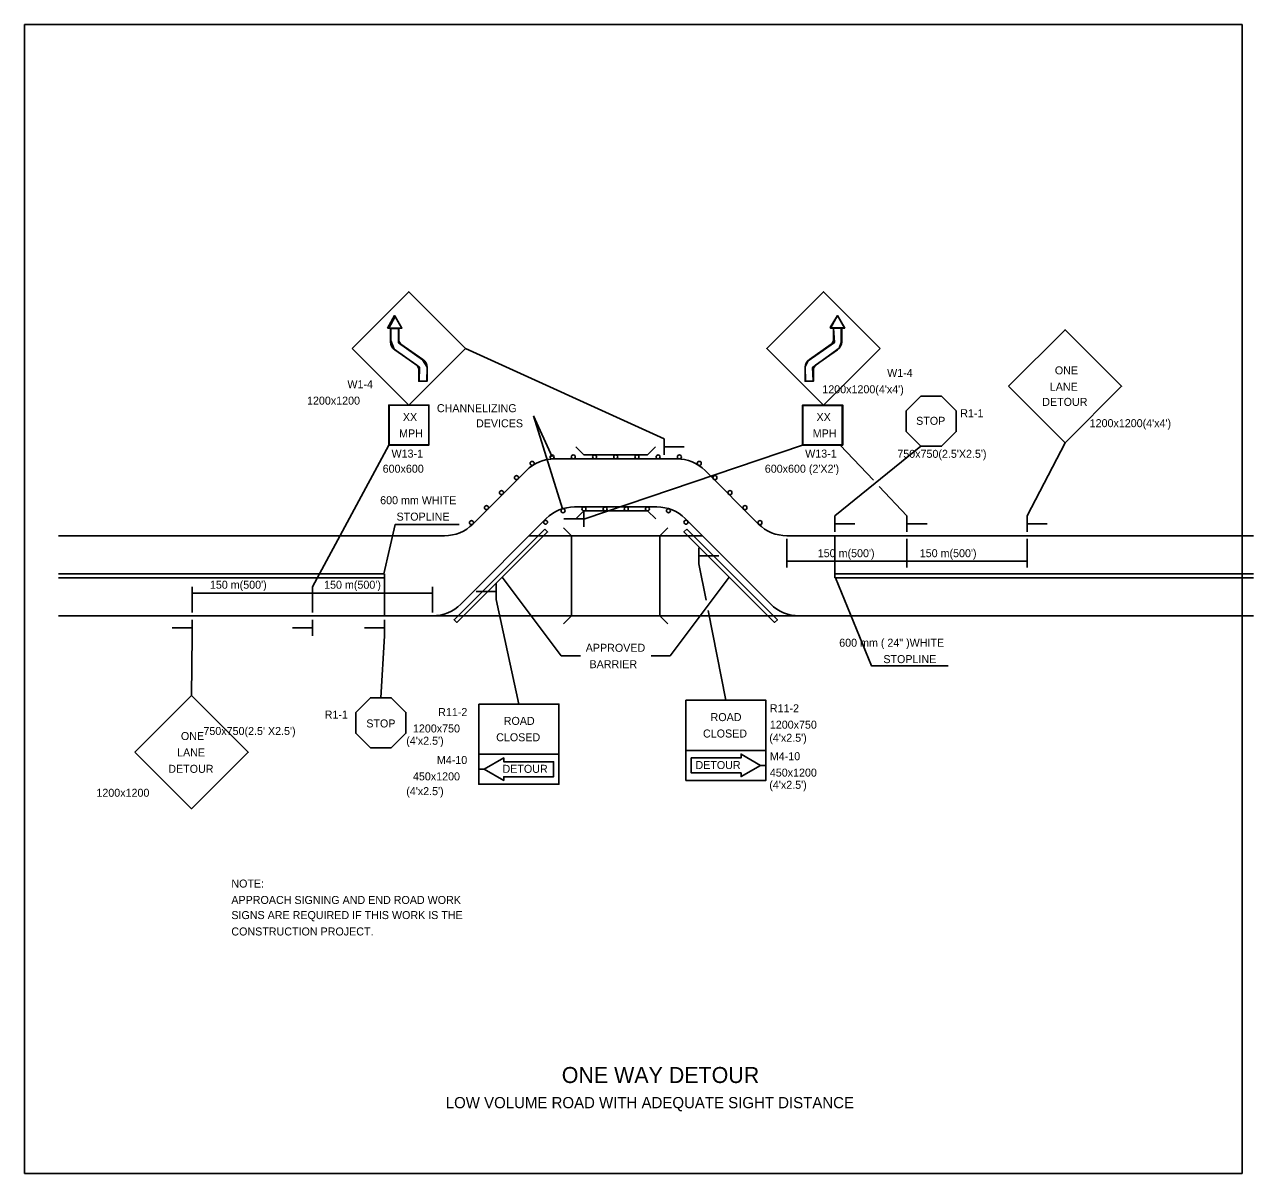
# Model space of a CAD drawing. Extents: x 1100953.92 to 1100956.78, y 416755.57 to 416757.4.
# Drawn here: x 1100955.102 to 1100955.742, y 416756.354 to 416756.952 of the extents above; entities that cross this region are included whole.
import ezdxf

# ---------------------------------------------------------------- set-up
doc = ezdxf.new("R2010")
doc.units = 0
for name, color, linetype in [('Level 10', 7, 'Continuous'), ('Level 3', 7, 'Continuous'), ('Level 33', 7, 'Continuous'), ('Level 4', 7, 'Continuous'), ('Level 6', 7, 'Continuous'), ('Level 7', 7, 'Continuous'), ('ORIG TOPO TEXT', 7, 'Continuous')]:
    doc.layers.add(name, color=color, linetype=linetype)

msp = doc.modelspace()

# ---------------------------------------------------------------- linework, layer by layer
at = {"layer": 'Level 10'}
for p, q in [((1100955.5233, 416756.79407), (1100955.5233, 416756.78787)), ((1100955.30647, 416756.7747), (1100955.29506, 416756.78271)), ((1100955.2983, 416756.78574), (1100955.3097, 416756.77774)), ((1100955.52219, 416756.78574), (1100955.51079, 416756.77774)), ((1100955.51402, 416756.7747), (1100955.52542, 416756.78271)), ((1100955.43523, 416756.73641), (1100955.43523, 416756.72808)), ((1100955.43523, 416756.73224), (1100955.44565, 416756.73224)), ((1100955.39353, 416756.69058), (1100955.39353, 416756.69891)), ((1100955.39353, 416756.69474), (1100955.38311, 416756.69474)), ((1100955.52408, 416756.6964), (1100955.52408, 416756.68807)), ((1100955.52408, 416756.69223), (1100955.5345, 416756.69223)), ((1100955.56158, 416756.6964), (1100955.56158, 416756.68807)), ((1100955.56158, 416756.69223), (1100955.572, 416756.69223)), ((1100955.62408, 416756.6964), (1100955.62408, 416756.68807)), ((1100955.62408, 416756.69223), (1100955.6345, 416756.69223)), ((1100955.45333, 416756.67971), (1100955.45333, 416756.67138)), ((1100955.45333, 416756.67554), (1100955.46375, 416756.67554)), ((1100955.34782, 416756.6528), (1100955.34782, 416756.66113)), ((1100955.34782, 416756.65696), (1100955.3374, 416756.65696)), ((1100955.1897, 416756.6339), (1100955.1897, 416756.64223)), ((1100955.2522, 416756.6339), (1100955.2522, 416756.64223)), ((1100955.2897, 416756.6339), (1100955.2897, 416756.64223)), ((1100955.1897, 416756.63807), (1100955.17928, 416756.63807)), ((1100955.2522, 416756.63807), (1100955.24178, 416756.63807)), ((1100955.2897, 416756.63807), (1100955.27928, 416756.63807))]:
    msp.add_line(p, q, dxfattribs=at)
for points in [[(1100955.27292, 416756.78347), (1100955.30238, 416756.75401), (1100955.33185, 416756.78347), (1100955.30238, 416756.81293), (1100955.27292, 416756.78347)], [(1100955.54757, 416756.78347), (1100955.5181, 416756.75401), (1100955.48864, 416756.78347), (1100955.5181, 416756.81293), (1100955.54757, 416756.78347)], [(1100955.29127, 416756.79407), (1100955.29877, 416756.79407), (1100955.29502, 416756.80057), (1100955.29127, 416756.79407)], [(1100955.52922, 416756.79407), (1100955.52172, 416756.79407), (1100955.52547, 416756.80057), (1100955.52922, 416756.79407)], [(1100955.29285, 416756.78697), (1100955.29285, 416756.79407), (1100955.29719, 416756.79407), (1100955.29719, 416756.78787)], [(1100955.52764, 416756.78697), (1100955.52764, 416756.79407), (1100955.5233, 416756.79407)], [(1100955.61435, 416756.76376), (1100955.64381, 416756.73429), (1100955.67327, 416756.76376), (1100955.64381, 416756.79322), (1100955.61435, 416756.76376)], [(1100955.31192, 416756.77347), (1100955.31192, 416756.76637), (1100955.30758, 416756.76637), (1100955.30758, 416756.77257)], [(1100955.50857, 416756.77347), (1100955.50857, 416756.76637), (1100955.51291, 416756.76637), (1100955.51291, 416756.77257)], [(1100955.56118, 416756.75094), (1100955.56118, 416756.74015), (1100955.5688, 416756.73252), (1100955.57959, 416756.73252), (1100955.58722, 416756.74015), (1100955.58722, 416756.75094), (1100955.57959, 416756.75857), (1100955.5688, 416756.75857), (1100955.56118, 416756.75094)], [(1100955.29197, 416756.75401), (1100955.29197, 416756.73317), (1100955.3128, 416756.73317), (1100955.3128, 416756.75401), (1100955.29197, 416756.75401)], [(1100955.3128, 416756.73317), (1100955.3128, 416756.75401), (1100955.29197, 416756.75401), (1100955.29197, 416756.73317), (1100955.3128, 416756.73317)], [(1100955.50729, 416756.73317), (1100955.52812, 416756.73317), (1100955.52812, 416756.75401), (1100955.50729, 416756.75401), (1100955.50729, 416756.73317)], [(1100955.50729, 416756.75401), (1100955.50729, 416756.73317), (1100955.52812, 416756.73317), (1100955.52812, 416756.75401), (1100955.50729, 416756.75401)], [(1100955.1599, 416756.57334), (1100955.18936, 416756.54388), (1100955.21883, 416756.57334), (1100955.18936, 416756.6028), (1100955.1599, 416756.57334)], [(1100955.2748, 416756.59403), (1100955.2748, 416756.58324), (1100955.28243, 416756.57562), (1100955.29322, 416756.57562), (1100955.30085, 416756.58324), (1100955.30085, 416756.59403), (1100955.29322, 416756.60166), (1100955.28243, 416756.60166), (1100955.2748, 416756.59403)], [(1100955.33881, 416756.59834), (1100955.33881, 416756.57229), (1100955.38048, 416756.57229), (1100955.38048, 416756.59834), (1100955.33881, 416756.59834)], [(1100955.44655, 416756.60034), (1100955.44655, 416756.5743), (1100955.48822, 416756.5743), (1100955.48822, 416756.60034), (1100955.44655, 416756.60034)], [(1100955.33881, 416756.57229), (1100955.33881, 416756.56448), (1100955.34159, 416756.56448), (1100955.35174, 416756.57034), (1100955.35174, 416756.56839), (1100955.3777, 416756.56839), (1100955.3777, 416756.56058), (1100955.35174, 416756.56058), (1100955.35174, 416756.55862), (1100955.34159, 416756.56448), (1100955.33881, 416756.56448), (1100955.33881, 416756.55667), (1100955.38048, 416756.55667), (1100955.38048, 416756.57229), (1100955.33881, 416756.57229)], [(1100955.34159, 416756.56448), (1100955.35174, 416756.57034), (1100955.35174, 416756.56839), (1100955.3777, 416756.56839), (1100955.3777, 416756.56058), (1100955.35174, 416756.56058), (1100955.35174, 416756.55862), (1100955.34159, 416756.56448)], [(1100955.48822, 416756.5743), (1100955.48822, 416756.56649), (1100955.48544, 416756.56649), (1100955.47529, 416756.57235), (1100955.47529, 416756.57039), (1100955.44933, 416756.57039), (1100955.44933, 416756.56258), (1100955.47529, 416756.56258), (1100955.47529, 416756.56063), (1100955.48544, 416756.56649), (1100955.48822, 416756.56649), (1100955.48822, 416756.55867), (1100955.44655, 416756.55867), (1100955.44655, 416756.5743), (1100955.48822, 416756.5743)], [(1100955.48544, 416756.56649), (1100955.47529, 416756.57235), (1100955.47529, 416756.57039), (1100955.44933, 416756.57039), (1100955.44933, 416756.56258), (1100955.47529, 416756.56258), (1100955.47529, 416756.56063), (1100955.48544, 416756.56649)]]:
    msp.add_lwpolyline(points, dxfattribs=at)
for centre, radius, start, end in [((1100955.29805, 416756.78697), 0.00521, 180, 234.94043), ((1100955.29979, 416756.78787), 0.0026, 180, 234.94043), ((1100955.5207, 416756.78787), 0.0026, 305.05957, 360), ((1100955.52243, 416756.78697), 0.00521, 305.05957, 360), ((1100955.30497, 416756.77257), 0.0026, 0, 54.94043), ((1100955.30671, 416756.77347), 0.00521, 0, 54.94043), ((1100955.51378, 416756.77347), 0.00521, 125.05957, 180), ((1100955.51551, 416756.77257), 0.0026, 125.05957, 180)]:
    msp.add_arc(centre, radius, start, end, dxfattribs=at)
at = {"layer": 'Level 3'}
for centre in [(1100955.36656, 416756.72363), (1100955.37694, 416756.727), (1100955.38798, 416756.72704), (1100955.39901, 416756.72704), (1100955.41004, 416756.72704), (1100955.42108, 416756.72704), (1100955.43211, 416756.72704), (1100955.44315, 416756.727), (1100955.45353, 416756.72363), (1100955.35841, 416756.71623), (1100955.46168, 416756.71623), (1100955.35061, 416756.70843), (1100955.46948, 416756.70843), (1100955.3428, 416756.70062), (1100955.38261, 416756.69901), (1100955.39353, 416756.69995), (1100955.40454, 416756.69995), (1100955.41555, 416756.69995), (1100955.42656, 416756.69995), (1100955.43748, 416756.69901), (1100955.47728, 416756.70062), (1100955.335, 416756.69282), (1100955.37352, 416756.69303), (1100955.44657, 416756.69303), (1100955.48509, 416756.69282)]:
    msp.add_circle(centre, 0.00104, dxfattribs=at)
at = {"layer": 'Level 33'}
for points in [[(1100955.29197, 416756.75401), (1100955.3128, 416756.75371), (1100955.3128, 416756.73335), (1100955.29223, 416756.73335), (1100955.29223, 416756.75382)], [(1100955.50758, 416756.75382), (1100955.52789, 416756.75382), (1100955.52789, 416756.73329), (1100955.50741, 416756.73329), (1100955.50741, 416756.75382)]]:
    msp.add_lwpolyline(points, close=True, dxfattribs=at)
at = {"layer": 'Level 4'}
msp.add_lwpolyline([(1100955.29522, 416756.80008), (1100955.29867, 416756.79404), (1100955.29194, 416756.79404)], close=True, dxfattribs=at)
at = {"layer": 'Level 7'}
for p, q in [((1100955.33185, 416756.78347), (1100955.43523, 416756.73641)), ((1100955.36722, 416756.7484), (1100955.37694, 416756.727)), ((1100955.36722, 416756.7484), (1100955.38229, 416756.70001)), ((1100955.29197, 416756.73317), (1100955.2522, 416756.65945)), ((1100955.50729, 416756.73317), (1100955.39353, 416756.69458)), ((1100955.5688, 416756.73252), (1100955.52408, 416756.6964)), ((1100955.52675, 416756.73317), (1100955.54409, 416756.71487)), ((1100955.64381, 416756.73429), (1100955.62408, 416756.6964)), ((1100955.37828, 416756.72599), (1100955.44181, 416756.72599)), ((1100955.33574, 416756.69208), (1100955.36355, 416756.71989)), ((1100955.45654, 416756.71989), (1100955.48435, 416756.69208)), ((1100955.54711, 416756.71168), (1100955.56158, 416756.6964)), ((1100955.43145, 416756.70099), (1100955.38863, 416756.70099)), ((1100955.3739, 416756.69489), (1100955.32943, 416756.65042)), ((1100955.49066, 416756.65042), (1100955.44619, 416756.69489)), ((1100955.12012, 416756.68598), (1100955.32101, 416756.68598)), ((1100955.36499, 416756.68598), (1100955.4551, 416756.68598)), ((1100955.49908, 416756.68598), (1100955.74184, 416756.68598)), ((1100955.49908, 416756.68434), (1100955.49908, 416756.6694)), ((1100955.52408, 416756.66411), (1100955.52408, 416756.68598)), ((1100955.56158, 416756.68434), (1100955.56158, 416756.6694)), ((1100955.62408, 416756.68434), (1100955.62408, 416756.6694)), ((1100955.45708, 416756.65245), (1100955.45333, 416756.67138)), ((1100955.49908, 416756.67268), (1100955.56158, 416756.67268)), ((1100955.56158, 416756.67268), (1100955.62408, 416756.67268)), ((1100955.12012, 416756.66619), (1100955.2897, 416756.66619)), ((1100955.2897, 416756.66619), (1100955.2897, 416756.64432)), ((1100955.52408, 416756.66619), (1100955.74184, 416756.66619)), ((1100955.12012, 416756.66411), (1100955.2897, 416756.66411)), ((1100955.1897, 416756.64596), (1100955.1897, 416756.65945)), ((1100955.2522, 416756.64596), (1100955.2522, 416756.65945)), ((1100955.3147, 416756.64596), (1100955.3147, 416756.65945)), ((1100955.52408, 416756.66411), (1100955.74184, 416756.66411)), ((1100955.1897, 416756.65617), (1100955.2522, 416756.65617)), ((1100955.2522, 416756.65617), (1100955.3147, 416756.65617)), ((1100955.35965, 416756.59834), (1100955.34782, 416756.6528)), ((1100955.46738, 416756.60034), (1100955.45815, 416756.64703)), ((1100955.3147, 416756.64432), (1100955.12012, 416756.64432)), ((1100955.3147, 416756.64432), (1100955.50539, 416756.64432)), ((1100955.74184, 416756.64432), (1100955.50539, 416756.64432)), ((1100955.18936, 416756.6028), (1100955.1897, 416756.6339)), ((1100955.28783, 416756.60166), (1100955.2897, 416756.6339))]:
    msp.add_line(p, q, dxfattribs=at)
for points in [[(1100955.3892, 416756.73223), (1100955.39353, 416756.72808), (1100955.42656, 416756.72808), (1100955.43073, 416756.73224)], [(1100955.43089, 416756.69476), (1100955.42656, 416756.69891), (1100955.39353, 416756.69891), (1100955.38936, 416756.69474)], [(1100955.32854, 416756.69175), (1100955.29525, 416756.69175), (1100955.28944, 416756.66619)], [(1100955.37308, 416756.68946), (1100955.32594, 416756.64231), (1100955.32741, 416756.64084), (1100955.37455, 416756.68798), (1100955.37308, 416756.68946)], [(1100955.38289, 416756.69015), (1100955.38705, 416756.68598), (1100955.38705, 416756.64432), (1100955.38289, 416756.64015)], [(1100955.4372, 416756.69015), (1100955.43303, 416756.68598), (1100955.43303, 416756.64432), (1100955.4372, 416756.64015)], [(1100955.44701, 416756.68946), (1100955.49415, 416756.64231), (1100955.49267, 416756.64084), (1100955.44553, 416756.68798), (1100955.44701, 416756.68946)], [(1100955.39164, 416756.62348), (1100955.38173, 416756.62348), (1100955.35098, 416756.66441)], [(1100955.42845, 416756.62348), (1100955.43836, 416756.62348), (1100955.4691, 416756.66441)], [(1100955.58303, 416756.61824), (1100955.5432, 416756.61824), (1100955.52439, 416756.66411)]]:
    msp.add_lwpolyline(points, dxfattribs=at)
for centre, start, end in [((1100955.37828, 416756.70516), 90, 135), ((1100955.44181, 416756.70516), 45, 90), ((1100955.38863, 416756.68016), 90, 135), ((1100955.43145, 416756.68016), 45, 90), ((1100955.32101, 416756.70682), 270, 315), ((1100955.49908, 416756.70682), 225, 270), ((1100955.3147, 416756.66515), 270, 315), ((1100955.50539, 416756.66515), 225, 270)]:
    msp.add_arc(centre, 0.02083, start, end, dxfattribs=at)
at = {"layer": 'ORIG TOPO TEXT'}
msp.add_lwpolyline([(1100955.10246, 416756.95198), (1100955.10246, 416756.35415), (1100955.73594, 416756.35415), (1100955.73594, 416756.95198), (1100955.10246, 416756.95198)], dxfattribs=at)
for points in [[(1100955.52547, 416756.80057), (1100955.52912, 416756.79411), (1100955.5217, 416756.79428)], [(1100955.29295, 416756.79387), (1100955.29295, 416756.78764), (1100955.29482, 416756.78301), (1100955.30797, 416756.77364), (1100955.30782, 416756.76654), (1100955.31181, 416756.76645), (1100955.31197, 416756.77379), (1100955.30954, 416756.77755), (1100955.29709, 416756.78645), (1100955.29709, 416756.79387)], [(1100955.52341, 416756.79401), (1100955.52735, 416756.79401), (1100955.52735, 416756.78651), (1100955.52623, 416756.78351), (1100955.51244, 416756.77359), (1100955.5127, 416756.7666), (1100955.50884, 416756.76646), (1100955.50856, 416756.77402), (1100955.51014, 416756.77698), (1100955.5238, 416756.78651)]]:
    msp.add_lwpolyline(points, close=True, dxfattribs=at)

# ---------------------------------------------------------------- texts
at = {"layer": 'Level 10'}
for s, height, p in [('ONE', 0.004165, (1100955.63853, 416756.76996)), ('W1-4', 0.004165, (1100955.55126, 416756.76865)), ('W1-4', 0.004165, (1100955.27042, 416756.76274)), ("1200x1200(4'x4')", 0.0041654, (1100955.51754, 416756.76012)), ('LANE', 0.004165, (1100955.6359, 416756.76143)), ('1200x1200', 0.004165, (1100955.24942, 416756.75421)), ('DETOUR', 0.004165, (1100955.63196, 416756.75356)), ('XX', 0.004165, (1100955.29929, 416756.74568)), ('XX', 0.004165, (1100955.51451, 416756.74568)), ('R1-1', 0.004165, (1100955.58931, 416756.74765)), ('STOP', 0.004165, (1100955.56635, 416756.74371)), ("1200x1200(4'x4')", 0.0041654, (1100955.65663, 416756.74248)), ('MPH', 0.004165, (1100955.29732, 416756.73715)), ('MPH', 0.004165, (1100955.51254, 416756.73715)), ('W13-1', 0.004165, (1100955.29338, 416756.72665)), ('W13-1', 0.004165, (1100955.50861, 416756.72665)), ("750x750(2.5'X2.5')", 0.0041654, (1100955.55655, 416756.72653)), ('600x600', 0.004165, (1100955.28879, 416756.71878)), ("600x600 (2'X2')", 0.0041654, (1100955.48761, 416756.71878)), ('R1-1', 0.004165, (1100955.25861, 416756.59083)), ('R11-2', 0.004165, (1100955.31766, 416756.59214)), ('R11-2', 0.004165, (1100955.49023, 416756.59411)), ('STOP', 0.004165, (1100955.28026, 416756.58623)), ('ROAD', 0.004165, (1100955.35178, 416756.58755)), ('ROAD', 0.004165, (1100955.45939, 416756.58952)), ('1200x750', 0.004165, (1100955.49023, 416756.58558)), ('ONE', 0.004165, (1100955.1838, 416756.57967)), ("750x750(2.5' X2.5')", 0.0041654, (1100955.19552, 416756.5823)), ('1200x750', 0.004165, (1100955.30454, 416756.58361)), ('CLOSED', 0.004165, (1100955.34784, 416756.57902)), ('CLOSED', 0.004165, (1100955.45546, 416756.58099)), ("(4'x2.5')", 0.004165, (1100955.48996, 416756.57876)), ("(4'x2.5')", 0.004165, (1100955.30105, 416756.57722)), ('LANE', 0.004165, (1100955.18183, 416756.57114)), ('M4-10', 0.004165, (1100955.317, 416756.56721)), ('M4-10', 0.004165, (1100955.49023, 416756.56917)), ('DETOUR', 0.004165, (1100955.17724, 416756.56261)), ('450x1200', 0.004165, (1100955.30454, 416756.55868)), ('DETOUR', 0.004165, (1100955.35113, 416756.56261)), ('DETOUR', 0.004165, (1100955.45152, 416756.56458)), ('450x1200', 0.004165, (1100955.49023, 416756.56064)), ("(4'x2.5')", 0.004165, (1100955.48996, 416756.55429)), ('1200x1200', 0.004165, (1100955.13984, 416756.55015)), ("(4'x2.5')", 0.004165, (1100955.30105, 416756.55099))]:
    msp.add_text(s, height=height, dxfattribs=at).set_placement(p)
at = {"layer": 'Level 6'}
for s, height, p in [('ONE WAY DETOUR', 0.0083307, (1100955.38196, 416756.4012)), ('LOW VOLUME ROAD WITH ADEQUATE SIGHT DISTANCE', 0.0058346, (1100955.3216, 416756.38807))]:
    msp.add_text(s, height=height, dxfattribs=at).set_placement(p)
at = {"layer": 'Level 7'}
for s, height, p in [('CHANNELIZING', 0.0041654, (1100955.317, 416756.75028)), ('DEVICES', 0.004165, (1100955.33735, 416756.7424)), ('600 mm WHITE', 0.0041654, (1100955.28748, 416756.70238)), ('STOPLINE', 0.004165, (1100955.29601, 416756.69385)), ("150 m(500')", 0.0041654, (1100955.51517, 416756.67482)), ("150 m(500')", 0.0041654, (1100955.56823, 416756.67482)), ("150 m(500')", 0.0041654, (1100955.19889, 416756.65841)), ("150 m(500')", 0.0041654, (1100955.25831, 416756.65841)), ('APPROVED', 0.004165, (1100955.39443, 416756.6256)), ('600 mm ( 24" )WHITE', 0.0041654, (1100955.52632, 416756.62823)), ('BARRIER', 0.004165, (1100955.3964, 416756.61707)), ('STOPLINE', 0.004165, (1100955.54929, 416756.6197)), ('NOTE:', 0.004165, (1100955.21005, 416756.5029)), ('APPROACH SIGNING AND END ROAD WORK', 0.0041654, (1100955.21005, 416756.49437)), ('SIGNS ARE REQUIRED IF THIS WORK IS THE', 0.0041654, (1100955.21005, 416756.4865)), ('CONSTRUCTION PROJECT.', 0.0041654, (1100955.21005, 416756.47797))]:
    msp.add_text(s, height=height, dxfattribs=at).set_placement(p)

doc.saveas('drawing.dxf')
